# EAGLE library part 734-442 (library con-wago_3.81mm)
Serie 734, Doppelstock-Stiftleisten Einlötstift abgewinkelt 1 x 1 mm / Series 734, Double-deck male headers Angled solder pin 1 x 1 mm Polzahl / Pole No.: 12 Rastermaß / Pitch: 3.81 mm Bemessungsspannung / Rated Voltage: 160 V Nennstrom / Nominal Current: 10 A Lötstiftlänge: / Solder Pin Length: 3.6 mm Farbe / Color: orange / orange Stand: 01.01.2012. Die jeweils aktuellen Daten zu diesem Artikel finden Sie in unserem Produktkatalog, den Sie unter www.wago.com einsehen können. As of: 01/01/2012. Please find the newest data for this article in our product catalogue, which can be viewed under www.wago.com.
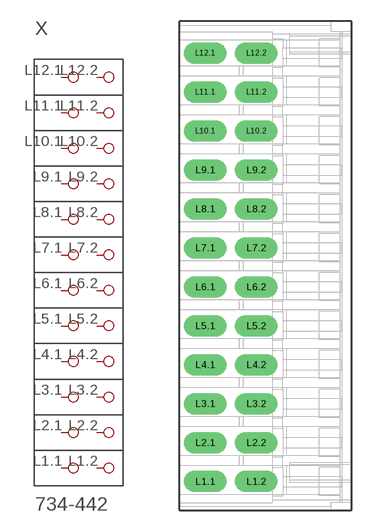
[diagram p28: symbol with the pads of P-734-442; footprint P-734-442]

Designator prefix X

## 734-442  [P-734-442]
L1.1  P1.1
L1.2  P1.2
L2.1  P2.1
L2.2  P2.2
L3.1  P3.1
L3.2  P3.2
L4.1  P4.1
L4.2  P4.2
L5.1  P5.1
L5.2  P5.2
L6.1  P6.1
L6.2  P6.2
L7.1  P7.1
L7.2  P7.2
L8.1  P8.1
L8.2  P8.2
L9.1  P9.1
L9.2  P9.2
L10.1  P10.1
L10.2  P10.2
L11.1  P11.1
L11.2  P11.2
L12.1  P12.1
L12.2  P12.2

## Footprint P-734-442 (pad centres in mm)
drill 1.4 long: L1.1 -5.9,-21.095; L1.2 -0.9,-21.095; L2.1 -5.9,-17.295; L2.2 -0.9,-17.295; L3.1 -5.9,-13.485; L3.2 -0.9,-13.485; L4.1 -5.9,-9.675; L4.2 -0.9,-9.675; L5.1 -5.9,-5.875; L5.2 -0.9,-5.875; L6.1 -5.9,-2.065; L6.2 -0.9,-2.065; L7.1 -5.9,1.755; L7.2 -0.9,1.755; L8.1 -5.9,5.565; L8.2 -0.9,5.565; L9.1 -5.9,9.375; L9.2 -0.9,9.375; L10.1 -5.9,13.185; L10.2 -0.9,13.185; L11.1 -5.9,16.995; L11.2 -0.9,16.995; L12.1 -5.9,20.805; L12.2 -0.9,20.805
